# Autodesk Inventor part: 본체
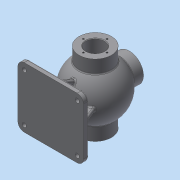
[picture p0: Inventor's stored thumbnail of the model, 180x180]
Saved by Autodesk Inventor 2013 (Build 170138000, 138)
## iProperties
Created: 2018-06
Part Number: 본체
Material: 일반
Document SubType Name: Modeling
Designer: Administrator
Density: 1 g/cm^3
Author: Administrator
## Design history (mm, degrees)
sketch "스케치1"
  geometry: L1 (0, 53)-(0, -53); A1 r 53 centre (0, 0) between (0, -53) and (0, 53); A2 r 43 centre (0, 0) between (0, -43) and (0, 43); 1 further point
  constraints: 4 point on circle, 2 centre point, 2 coincident, 2 end point, 2 point on line, 1 midpoint, 1 vertical
  dimensions: "d0" = 106 diameter of A1; "d1" = 86 diameter of A2
revolve "회전1" sketch "스케치1" stored, may be unused: angle "d2" = 90 deg
node "작업 평면1"
sketch "스케치2"
  geometry: C1 r 31 at (0, 0); 1 further point
  constraints: 1 centre point, 1 coincident
  dimensions: "d4" = 62 diameter of C1
extrude "돌출1" join sketch "스케치2" stored distance "d5" = 10; taper "d6" = 0 deg
hole "구멍1" diameter "d9" = 35; stored, may be unused: countersink angle "d13" = 90 deg, drill point angle "d15" = 118 deg; dims "d7" = 10, "d8" = 10, "d10" = 6, "d11" = 4, "d12" = 2, "d14" = 8
sketch "스케치3"
  geometry: C1 r 17.5 at (0, 0) reference; 1 further point
  constraints: 1 vertical alignment
  dimensions: "d16" = 22.5 distance of C1.centre point (0, 22.5)
hole "구멍2" sketch "스케치3" at (0, 22.5) diameter "d17" = 3.242; stored, may be unused: countersink angle "d21" = 90 deg, drill point angle "d23" = 118 deg; dims "d18" = 12, "d19" = 4, "d20" = 2, "d22" = 15
node "작업 평면2"
sketch "스케치4"
  geometry: C1 r 27 at (0, 0); 1 further point
  constraints: 1 centre point, 1 coincident
  dimensions: "d28" = 54 diameter of C1
extrude "돌출2" join sketch "스케치4" stored distance "d29" = 10; taper "d30" = 0 deg
hole "구멍4" diameter "d42" = 26; stored, may be unused: countersink angle "d46" = 90 deg, drill point angle "d48" = 0 deg; dims "d40" = 10, "d41" = 10, "d43" = 9, "d44" = 4, "d45" = 2, "d47" = 11
sketch "스케치5"
  geometry: C1 r 13 at (0, 0) reference; 1 further point
  constraints: 1 horizontal alignment
  dimensions: "d49" = 20 distance of C1.centre point (-20, 0)
hole "구멍5" sketch "스케치5" at (-20, 0) diameter "d50" = 3.242; stored, may be unused: countersink angle "d54" = 90 deg, drill point angle "d56" = 118 deg; dims "d51" = 9, "d52" = 4, "d53" = 2, "d55" = 11
sketch "스케치6"
  geometry: C1 r 17.5 at (0, 0) reference; 1 further point
  constraints: 1 vertical alignment
  dimensions: "d60" = 24 distance of C1.centre point (0, 24)
hole "구멍6" sketch "스케치6" at (0, 24) diameter "d61" = 3.242; stored, may be unused: countersink angle "d65" = 90 deg, drill point angle "d67" = 118 deg; dims "d62" = 16, "d63" = 4, "d64" = 2, "d66" = 19
node "작업 평면3"
sketch "스케치7"
  geometry: L1 (-62.5, -57.5)-(62.5, -57.5); L2 (62.5, -57.5)-(62.5, 57.5); L3 (62.5, 57.5)-(-62.5, 57.5); L4 (-62.5, 57.5)-(-62.5, -57.5); L5 (-62.5, -57.5)-(62.5, 57.5); L6 (62.5, -57.5)-(-62.5, 57.5); 1 further point
  constraints: 12 end point, 2 midpoint, 2 parallel, 1 horizontal, 1 perpendicular
  dimensions: "d72" = 125 distance of L3.end L2.end; "d73" = 115 distance of L2.end L1.end
extrude "돌출3" join sketch "스케치7" distance "d74" = 10; taper "d75" = 0 deg
sketch "스케치12"
  geometry: L1 (-62.5, 57.5)-(-62.5, -57.5) reference; L2 (52.5, -4)-(-52.5, -4); L3 (-52.5, -4)-(-52.5, 4); L4 (-52.5, 4)-(52.5, 4); L5 (52.5, 4)-(52.5, -4); L6 (52.5, -4)-(-52.5, 4); L7 (-52.5, -4)-(52.5, 4); 1 further point
  constraints: 12 end point, 2 midpoint, 2 parallel, 1 horizontal, 1 perpendicular
  dimensions: "d85" = 8 distance of L2.end L3.end; "d87" = 10 distance between parallel lines of L1 L3
extrude "돌출5" join sketch "스케치12" stored distance "d88" = 8; taper "d89" = 0 deg
feature "면 기울기1" dims angle "d90" = 22 deg
sketch "스케치13"
  geometry: L1 (-75, -47.5)-(-40.891, -33.719); L2 (-75, -57.5)-(-75, 57.5) reference; L3 (-85, -57.5)-(-75, -57.5) reference; A1 r 53 centre (0, 0) between (31, -42.988) and (-31, -42.988) reference; 1 further point
  constraints: 2 end point, 1 point on circle, 1 point on line
  dimensions: "d91" = 10 distance from line of L3 L1.start; "d92" = 112 deg angle of L2 L1
feature "리브1" sketch "스케치13" dims "d93" = 1, "d94" = 8, "d95" = 0, "d96" = 0, "d97" = 1, "d98" = 1
node "작업 평면4"
sketch "스케치14"
  geometry: C1 r 18.5 at (0, 0); 1 further point
  constraints: 1 centre point, 1 coincident
  dimensions: "d100" = 37 diameter of C1
extrude "돌출6" cut sketch "스케치14" distance "d101" = 1.75; taper "d102" = 0 deg
chamfer "모따기1" distance "d103" = 1; stored, may be unused: second distance "d104" = 2, angle "d105" = 45 deg
fillet "모깎기1" dims "d106" = 12
sketch "스케치15"
  geometry: A1 r 12 centre (50.5, 45.5) between (62.5, 45.5) and (50.5, 57.5) reference; 2 further points
  constraints: 1 coincident
hole "구멍7" sketch "스케치15" at (50.5, 45.5) diameter "d107" = 8; stored, may be unused: countersink angle "d111" = 90 deg, drill point angle "d113" = 0 deg; dims "d108" = 16, "d109" = 12, "d110" = 3, "d112" = 10
fillet "모깎기2" dims "d120" = 3
fillet "모깎기3" dims "d121" = 3
fillet "모깎기4" dims "d122" = 3
node "작업 평면5"
sketch "스케치16"
  geometry: L1 (-65, -27)-(-47.286, -27) reference; L2 (-65, -27)-(-65, 27) reference; 2 further points
  constraints: 1 other
  dimensions: "d124" = 27 distance from line of point (-55, 0) L1; "d125" = 10 distance from line of point (-55, 0) L2
feature "엠보싱1" sketch "스케치16" dims "d0" = 106, "d1" = 86, "d19" = 4, "d126" = 0.5, "d127" = 0
node "솔리드1"
pattern_circular "원형 패턴1" dims angle "d25" = 360 deg
pattern_circular "원형 패턴2" dims angle "d58" = 360 deg
mirror "대칭2"
pattern_circular "원형 패턴3" dims angle "d69" = 360 deg
mirror "대칭4"
pattern_linear "직사각형 패턴1" dims "d116" = 91, "d119" = 101
other parameters: "d3" = 68, "d27" = 65, "d71" = -85, "d99" = -52, "d123" = -27
